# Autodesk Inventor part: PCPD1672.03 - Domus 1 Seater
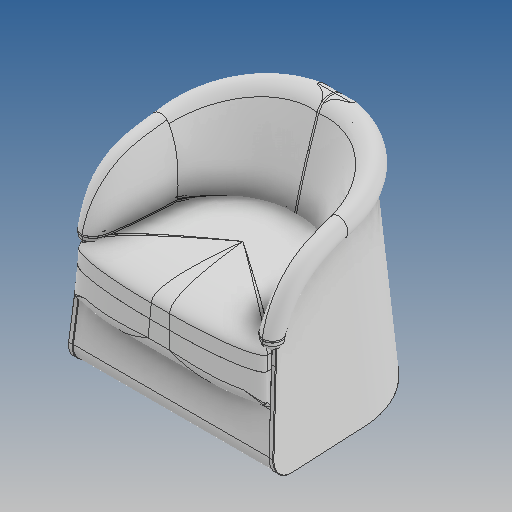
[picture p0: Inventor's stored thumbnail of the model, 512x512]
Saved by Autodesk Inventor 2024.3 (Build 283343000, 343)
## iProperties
Created: 2025-04
Part Number: PCPD1672.03 - Domus 1 Seater
Material: Generic
Description: STEP AP203
Document SubType Name: Modeling
Designer: rohit.darbha
Density: 1 g/cm^3
Appearance: Default
Title: PCPD1672.03 - Domus 1 Seater.STEP
Sending System: SolidWorks 2025
Preprocessor: SwSTEP 2.0
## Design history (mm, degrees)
feature "Domus Facelift Seat - version 3_1 Seater_1:1"
feature "Domus Facelift Seat - version 3_1 Seater_1:2"
feature "Domus Facelift Seat - version 3_1 Seater_1:3"
feature "Domus Facelift Seat - version 3_1 Seater_1:4"
feature "Domus Facelift Seat - version 3_1 Seater_1:5"
feature "Domus Facelift Seat - version 3_1 Seater_1:6"
feature "Domus Facelift Seat - version 3_1 Seater_1:7"
feature "Domus Facelift Seat - version 3_1 Seater_1:8"
feature "Domus Facelift Seat - version 3_1 Seater_1:9"
feature "Domus Facelift Seat - version 3_1 Seater_1:10"
feature "Domus Facelift Seat - version 3_1 Seater_1:11"
feature "Domus Facelift Seat - version 3_1 Seater_1:12"
feature "Domus Facelift Seat - version 3_1 Seater_1:13"
feature "Domus Facelift Seat - version 3_1 Seater_1:14"
feature "Domus Facelift Seat - version 3_1 Seater_1:15"
feature "Domus Facelift Seat - version 3_1 Seater_1:16"
feature "Domus Facelift Seat - version 3_1 Seater_1:17"
feature "Domus Facelift Seat - version 3_1 Seater_1:18"
feature "Domus Facelift Seat - version 3_1 Seater_1:19"
feature "Domus Facelift Seat - version 3_1 Seater_1:20"
feature "Domus Facelift Seat - version 3_1 Seater_1:21"
feature "Domus Facelift Seat - version 3_1 Seater_1:22"
feature "Domus Facelift Seat - version 3_1 Seater_1:23"
feature "Domus Facelift Seat - version 3_1 Seater_1:24"
feature "Domus Facelift Backrest - version 3_1 Seater_2:1"
feature "Domus Facelift Backrest - version 3_1 Seater_2:2"
feature "Domus Facelift Backrest - version 3_1 Seater_2:3"
feature "Domus Facelift Backrest - version 3_1 Seater_2:4"
feature "Domus Facelift Backrest - version 3_1 Seater_2:5"
feature "Domus Facelift Backrest - version 3_1 Seater_2:6"
feature "Domus Facelift Backrest - version 3_1 Seater_2:7"
feature "Domus Facelift Backrest - version 3_1 Seater_2:8"
feature "Domus Facelift Backrest - version 3_1 Seater_2:9"
feature "Domus Facelift Backrest - version 3_1 Seater_2:10"
feature "Domus Facelift Backrest - version 3_1 Seater_2:11"
feature "Domus Facelift Backrest - version 3_1 Seater_2:12"
feature "Domus Facelift Backrest - version 3_1 Seater_2:13"
body "Solid1"
body "Solid2"
body "Solid3"
body "Solid4"
body "Solid5"
body "Solid6"
body "Solid7"
body "Solid8"
body "Solid9"
body "Solid10"
body "Solid11"
body "Solid12"
body "Solid13"
body "Solid14"
body "Solid15"
body "Solid16"
body "Solid17"
body "Solid18"
body "Solid19"
body "Solid20"
body "Solid21"
body "Solid22"
body "Solid23"
body "Solid24"
body "Solid25"
body "Solid26"
body "Solid27"
body "Solid28"
body "Solid29"
body "Solid30"
body "Solid31"
body "Solid32"
body "Solid33"
body "Solid34"
body "Solid35"
body "Solid36"
body "Solid37"
